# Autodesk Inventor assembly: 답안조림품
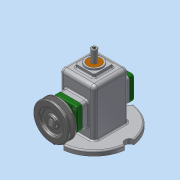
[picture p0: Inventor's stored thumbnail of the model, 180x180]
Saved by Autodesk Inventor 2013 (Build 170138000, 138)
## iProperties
Created: 2018-07
Part Number: 답안조림품
Document SubType Name: Assembly
Designer: Administrator
Author: Administrator
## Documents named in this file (16)
- C:\Users\Administrator\Desktop\480708V1016\답안조림품.iam
- C:\Users\Administrator\Desktop\480708V1016\본체.ipt
- C:\Users\Administrator\Desktop\480708V1016\편심축.ipt
- C:\Users\Administrator\Desktop\480708V1016\키 4x4x10.ipt
- C:\Users\Administrator\Desktop\480708V1016\링크.ipt
- C:\Users\Administrator\Desktop\480708V1016\베어링 12x32x10.ipt
- C:\Users\Administrator\Desktop\480708V1016\앞커버.ipt
- C:\Users\Administrator\Desktop\480708V1016\뒤커버.ipt
- C:\Users\Administrator\Desktop\480708V1016\오일 실 12 25 7.ipt
- C:\Users\Administrator\Desktop\480708V1016\V벨트풀리.ipt
- C:\Users\Administrator\Desktop\480708V1016\볼트 M4.ipt
- C:\Users\Administrator\Desktop\480708V1016\멈춤나사 M3x8.ipt
- C:\Users\Administrator\Desktop\480708V1016\슬라이드.ipt
- C:\Users\Administrator\Desktop\480708V1016\고정핀 1.2x8.ipt
- C:\Users\Administrator\Desktop\480708V1016\핀 5x18.ipt
- C:\Users\Administrator\Desktop\480708V1016\부시.ipt
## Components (3 placed, 3 different names)
1. V벨트풀리:1
2. 고정핀 1.2x8:1
3. 핀 5x18:1
